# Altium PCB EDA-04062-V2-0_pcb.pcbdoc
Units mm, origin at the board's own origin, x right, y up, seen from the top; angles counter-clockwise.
Board outline 34 x 34 mm, 2 copper layers (Top Layer, Bottom Layer), stack 0.98 mm thick; 20 components, 9 nets, 240 pads, 8 vias.
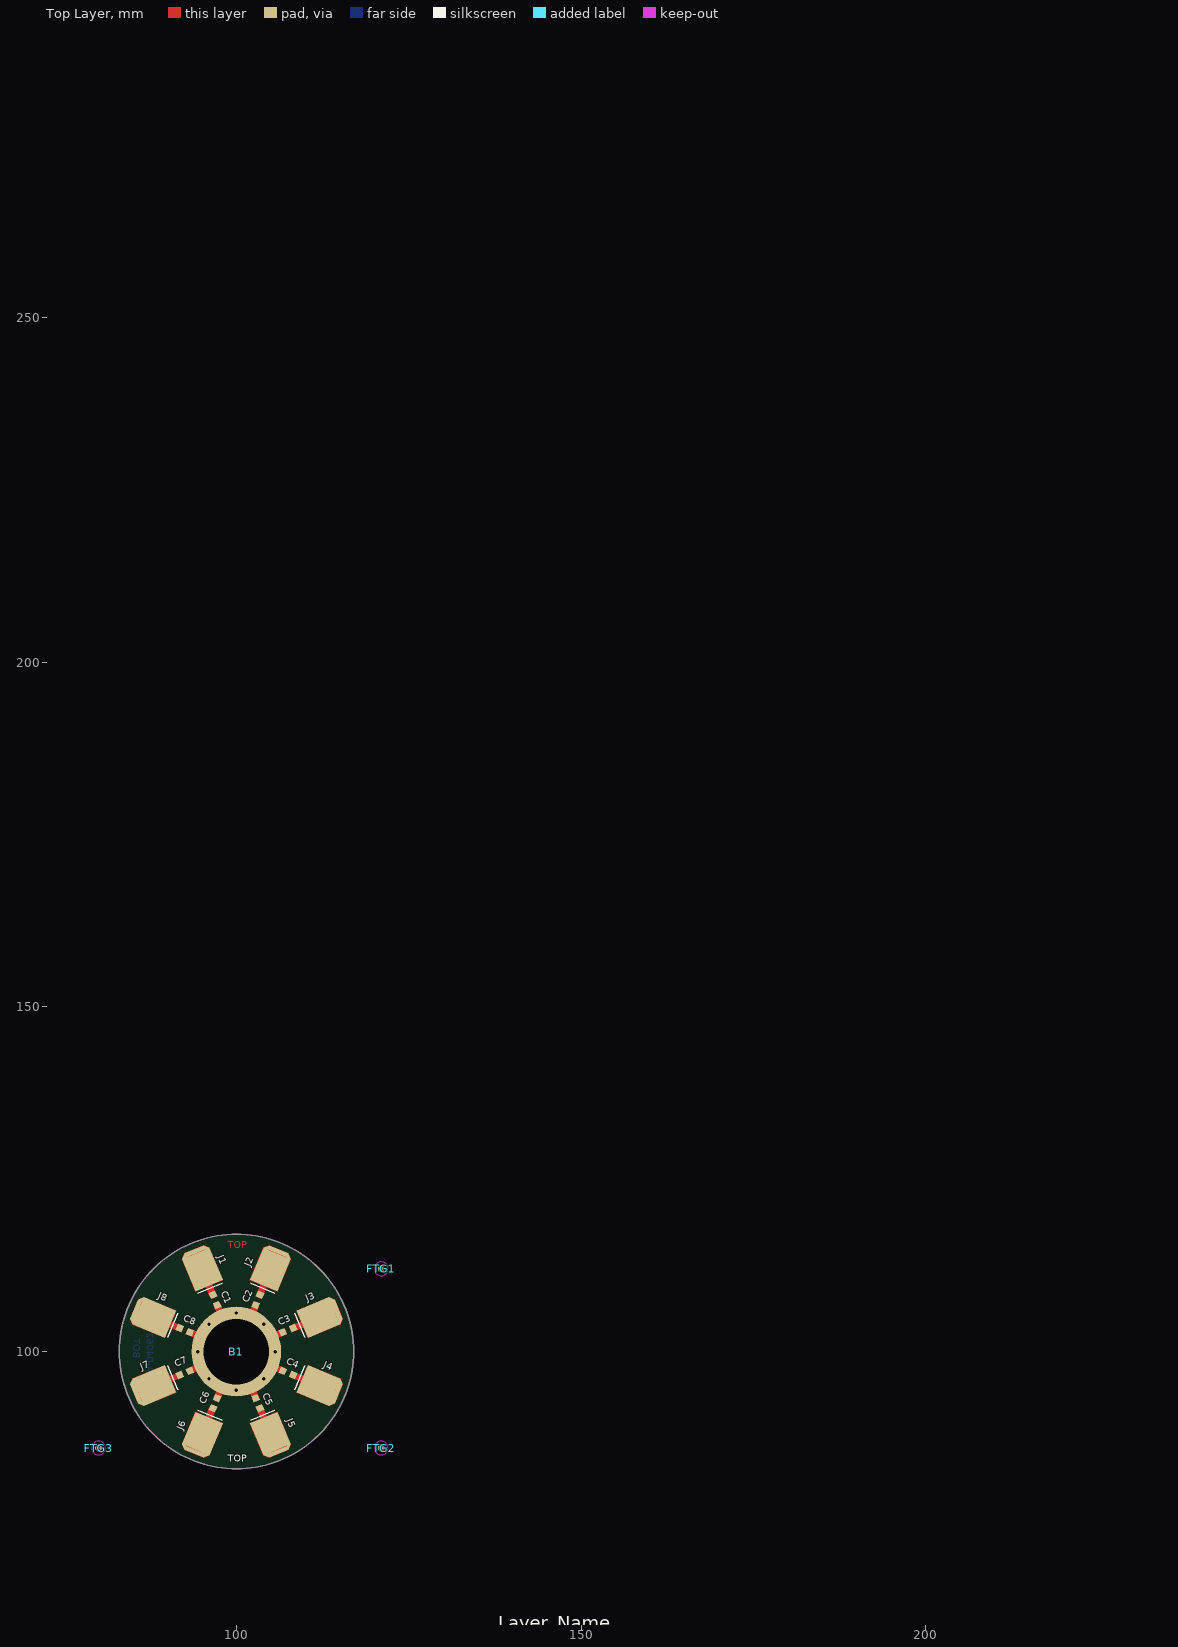
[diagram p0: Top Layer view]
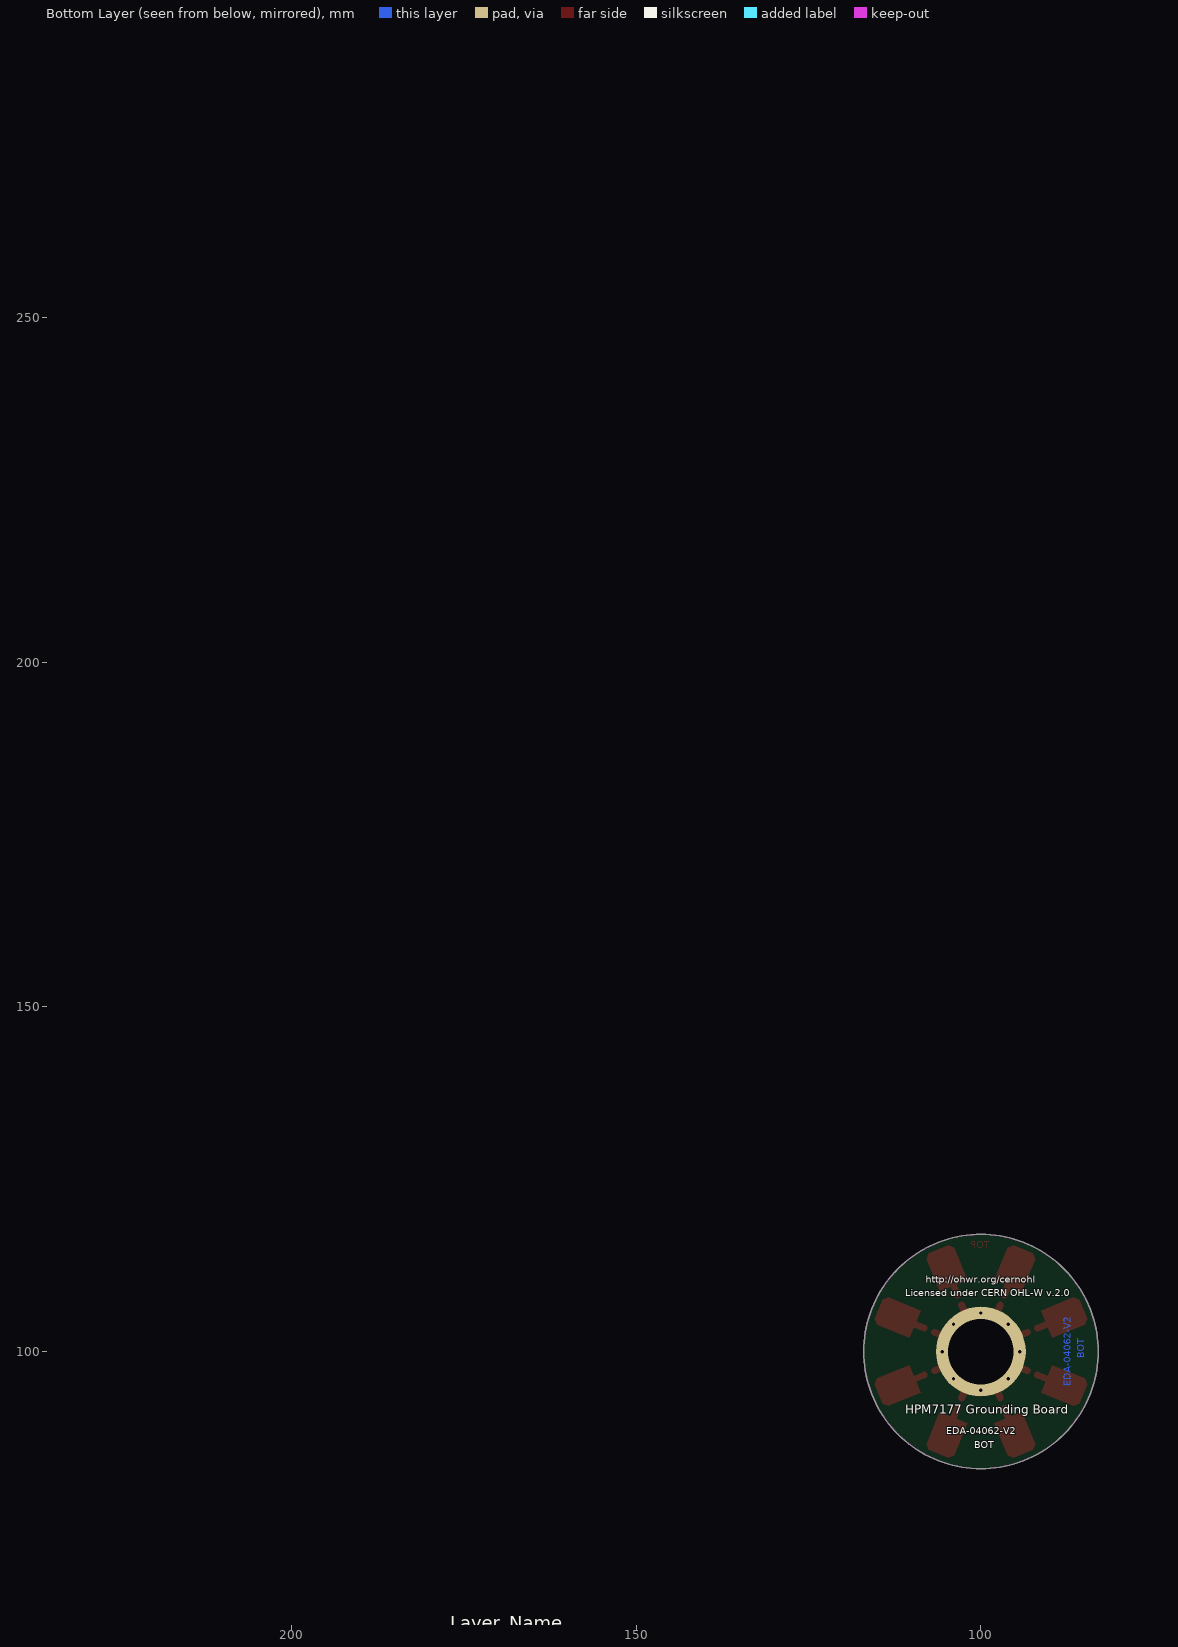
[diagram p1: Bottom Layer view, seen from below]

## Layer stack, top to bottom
Top Solder: solder mask 0.01, Solder Resist, Dk 3.5
Top Layer: signal copper 0.035
Dielectric 1: dielectric 0.91, FR-4, Dk 4.8
Bottom Layer: signal copper 0.035
Bottom Solder: solder mask 0.01, Solder Resist, Dk 3.5

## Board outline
100,83 cw(c100,100) 83,100 cw(c100,100) 100,117 cw(c100,100) 117,100 cw(c100,100)

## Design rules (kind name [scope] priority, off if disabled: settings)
BoardOutlineClearance "Inverted Serig" [((ObjectKind = 'Text') And (IsTextInverted = 'True')) And ((AsMM(InvertedTextBorder) < 0.2) or (AsMM(TextHeight) < 1.5))] p1: gap=2500 ignorepadtopadclearanceinfootprint=FALSE
BoardOutlineClearance "Uncheck Plat" [(PadIsPlated = 'True') And ((HoleDiameter >= PadXSize_AllLayers ) OR (HoleDiameter >= PadYSize_AllLayers))] p2: gap=2500 ignorepadtopadclearanceinfootprint=FALSE
BoardOutlineClearance "Defaut Serig" [(((Layer = 'TopOverlay')  And (StrokeFont = 'Default')) or ((Layer = 'BottomOverlay')  And (StrokeFont = 'Default'))) and not IsTextInverted = 'True'] p3: gap=2500 ignorepadtopadclearanceinfootprint=FALSE
Clearance [All] p1: gap=0.5 ignorepadtopadclearanceinfootprint=FALSE
ComponentClearance ComponentClearance_Overlapping [InComponentClass('NotMounted')] p1: gap=0 collisioncheckmode=3 verticalgap=0 showdistances=FALSE
ComponentClearance [All] p2: gap=0.2 collisioncheckmode=3 verticalgap=0.2 showdistances=FALSE
DiffPairsRouting [All] p1: maxlimit=0.457 minlimit=0.457 mostfreqgap=0.457 toplayer_minwidth=0.229 toplayer_maxwidth=0.229 toplayer_prefwidth=0.229 bottomlayer_minwidth=0.229 bottomlayer_maxwidth=0.229 bottomlayer_prefwidth=0.229 maxuncoupledlength=2.54
FabricationTestPointUsage TestPointUsage [All] p1: valid=0 allowmultiple=FALSE
FabricationTestpoint Testpoint [All] p1: side=3 testpointundercomponent=TRUE minsize=1.016 maxsize=2.54 preferedsize=1.524 minholesize=0 maxholesize=1.016 preferedholesize=0.813 testpointgrid=0.025 allowsidetop=TRUE allowsidebottom=TRUE usegrid=TRUE gridtolerance=0
Height [All] p1: minheight=0 maxheight=25 prefheight=10
HoleSize [All] p1: absolutevalues=TRUE maxlimit=10 minlimit=0.5 maxpercent=80.000 minpercent=20.000
HoleToHoleClearance [All] p1: gap=0.2 allowstackedmicrovias=TRUE
MinimumAnnularRing MinimumAnnularRing_Via [IsVia] p1: minimumring=0.25
MinimumAnnularRing [All] p2: minimumring=0.35
MinimumSolderMaskSliver [All] p1: minsoldermaskwidth=0.25
PermittedLayers [All] p1: toplayerpermitted=TRUE bottomlayerpermitted=TRUE
PlaneClearance [All] p1: clearance=0.5
PlaneConnect PlaneConnect_Direct [InPadClass('Mounting') or IsVia] p1: planeconnectstyle=Direct reliefexpansion=0.508 reliefentries=4 reliefconductorwidth=0.254 reliefairgap=0.254
PlaneConnect [All] p2: planeconnectstyle=Relief reliefexpansion=0.3 reliefentries=4 reliefconductorwidth=0.5 reliefairgap=0.2
PolygonConnect PolygonConnect_Direct [InPadClass('Mounting') or IsVia] p1: connectstyle=Direct reliefconductorwidth=0.254 reliefentries=4 polygonreliefangle="90 Angle" airgapwidth=0.254
PolygonConnect [All] p2: connectstyle=Relief reliefconductorwidth=0.5 reliefentries=4 polygonreliefangle="90 Angle" airgapwidth=0.2
RoomDefinition grounding_pcb [InComponentClass('grounding_pcb')] p1: confinementstyle=ConfineIn formatcopy=TRUE lockcomponents=FALSE outline 78.5,80.5 122.5,80.5 122.5,116.5 78.5,116.5
RoutingVias RoutingVias_NoNet [Not IsElectrical] p1: holewidth=0 width=0 viastyle="Through Hole" minholewidth=0 minwidth=0 maxholewidth=0 maxwidth=0
RoutingVias [All] p2: holewidth=0.5 width=1 viastyle="Through Hole" minholewidth=0.5 minwidth=1 maxholewidth=0.5 maxwidth=1
SilkToSilkClearance [All] p1: silktosilkclearance=0.2
SilkToSolderMaskClearance SilkscreenOverComponentPads [IsPad] p1: minsilkscreentomaskgap=0.225 clearancetoexposedcopper=TRUE
SolderMaskExpansion [All] p1: expansion=0 istentingtop=FALSE
ViasUnderSMD [All] p1: allowed=FALSE
Width [All] p1: maxlimit=2.5 minlimit=0.8 preferedwidth=0.8
18 further rules are at their usual default settings.

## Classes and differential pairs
component class NotMounted: B1

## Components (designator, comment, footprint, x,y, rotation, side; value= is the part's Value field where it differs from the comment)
B1 "Plated Hole" MTG950H1300V8P 100,100 r0 top
C1 "10nF" CAPC1608X87N 96.9,107.483 r292.5 top
C2 "10nF" CAPC1608X87N 103.1,107.483 r247.5 top
C3 "10nF" CAPC1608X87N 107.483,103.1 r202.5 top
C4 "10nF" CAPC1608X87N 107.483,96.9 r157.5 top
C5 "10nF" CAPC1608X87N 103.1,92.517 r112.5 top
C6 "10nF" CAPC1608X87N 96.9,92.517 r67.5 top
C7 "10nF" CAPC1608X87N 92.517,96.9 r22.5 top
C8 "10nF" CAPC1608X87N 92.517,103.1 r337.5 top
FTG1 "Use only in PCB" FIDUCIAL_TOP_C100-200 121,112 r90 top
FTG2 "Use only in PCB" FIDUCIAL_TOP_C100-200 121,86 r90 top
FTG3 "Use only in PCB" FIDUCIAL_TOP_C100-200 80,86 r90 top
J1 "" LAIRD_BMI-C-004 94.949,112.195 r112.5 top
J2 "" LAIRD_BMI-C-004 105.051,112.195 r67.5 top
J3 "" LAIRD_BMI-C-004 112.195,105.051 r22.5 top
J4 "" LAIRD_BMI-C-004 112.195,94.949 r337.5 top
J5 "" LAIRD_BMI-C-004 105.051,87.805 r292.5 top
J6 "" LAIRD_BMI-C-004 94.949,87.805 r247.5 top
J7 "" LAIRD_BMI-C-004 87.805,94.949 r202.5 top
J8 "" LAIRD_BMI-C-004 87.805,105.051 r157.5 top

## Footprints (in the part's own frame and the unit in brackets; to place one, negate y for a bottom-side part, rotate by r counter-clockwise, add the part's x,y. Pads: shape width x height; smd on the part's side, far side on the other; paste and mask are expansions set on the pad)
CAPC1608X87N [mm] "Chip Capacitor, Body 1.6x0.8mm IPC Medium Density"
  rect 0.95x1 smd: 1(-0.8,0) 2(0.8,0)
  body extent -0.87,-0.47 0.88,0.48, height 0.87
FIDUCIAL_TOP_C100-200 [mm] "Round Fiducial Target, Top Layer, 1.0mm, Top Solder 2.0mm, Keepout =2.0mm"
  round 1 smd paste-0.51 mask+0.5: FTG2(0,0)
  Top Layer keep-out circle w0.1: c0,0 r1
LAIRD_BMI-C-004 [mm] "Surface Mount Standard Precision EMI Gasket Grounding Contact, Body 5.97mm x 4.31mm"
  rect 5.08x4.31 smd: 1(-0.325,0)
  rect 0.46x0.919 smd rot 45: 1(2.378,1.667)
  rect 0.46x0.919 smd rot 135: 1(2.378,-1.667)
  rect 0.65x3.01 smd: 1(2.54,0)
  Top Layer region: -2.865,2.155 2.215,2.155 2.865,1.505 2.865,-1.505 2.865,-1.505 2.215,-2.155 -2.865,-2.155
  silkscreen extent -3.23,-1.91 -3.23,1.91, body extent -3.25,-2.16 2.72,2.16, height 5.17
MTG950H1300V8P [mm] "Plated Through Hole: Hole Dia.=9.5mm Pad Dia.=13.0mm + 8 Via Dia.=0.5mm"
  round 13 hole 9.5: 1(0,0)

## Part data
B1: library part PLATED_HOLE9.5_PAD13.0_8VIA, "Single Terminal Socket"
C1 C2 C3 C4 C5 C6 C7 C8: library part CC0603_10NF_250V_10%_X7R_KEMET_C0603C103KARACAUTO, "Non-polarised capacitor", Case=0603, Manufacturer=KEMET, Manufacturer Part Number=C0603C103KARACAUTO, Tolerance=±10%, Voltage=250V
FTG1 FTG2 FTG3: library part FIDUCIAL_TARGET_C100-200, "Fiducial Target"
J1 J2 J3 J4 J5 J6 J7 J8: library part LAIRD_BMI-C-004, "Spring Contact", Manufacturer=LAIRD

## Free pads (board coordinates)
  round 3.5 on Mech9: 1(78,66.1) 1(230,66.1)
  round 1 on Mech9: 1(80,86) 1(121,86) 1(121,112)
  round 0.8 on Mech9: 1(84.64,92.297) 1(84.64,145.897) 1(84.64,199.497) 1(84.64,253.097) 1(85.357,91.273) 1(85.357,144.873) 1(85.357,198.473) 1(85.357,252.073) 1(86.074,90.249) 1(86.074,143.849) 1(86.074,197.449) 1(86.074,251.049) 1(86.791,89.225) 1(86.791,142.825) 1(86.791,196.425) 1(86.791,250.025) 1(87.508,88.201) 1(87.508,141.801) 1(87.508,195.401) 1(87.508,249.001) 1(97.5,117) 1(97.5,170.6) 1(97.5,224.2) 1(97.5,277.8) 1(98.75,117) 1(98.75,170.6) 1(98.75,224.2) 1(98.75,277.8) 1(100,117) 1(100,170.6) 1(100,224.2) 1(100,277.8) 1(101.25,117) 1(101.25,170.6) 1(101.25,224.2) 1(101.25,277.8) 1(102.5,117) 1(102.5,170.6) 1(102.5,224.2) 1(102.5,277.8) 1(112.492,88.201) 1(112.492,141.801) 1(112.492,195.401) 1(112.492,249.001) 1(113.209,89.225) 1(113.209,142.825) 1(113.209,196.425) 1(113.209,250.025) 1(113.926,90.249) 1(113.926,143.849) 1(113.926,197.449) 1(113.926,251.049) 1(114.643,91.273) 1(114.643,144.873) 1(114.643,198.473) 1(114.643,252.073) 1(115.36,92.297) 1(115.36,145.897) 1(115.36,199.497) 1(115.36,253.097) 1(138.64,92.297) 1(138.64,145.897) 1(138.64,199.497) 1(138.64,253.097) 1(139.357,91.273) 1(139.357,144.873) 1(139.357,198.473) 1(139.357,252.073) 1(140.074,90.249) 1(140.074,143.849) 1(140.074,197.449) 1(140.074,251.049) 1(140.791,89.225) 1(140.791,142.825) 1(140.791,196.425) 1(140.791,250.025) 1(141.508,88.201) 1(141.508,141.801) 1(141.508,195.401) 1(141.508,249.001) 1(151.5,117) 1(151.5,170.6) 1(151.5,224.2) 1(151.5,277.8) 1(152.75,117) 1(152.75,170.6) 1(152.75,224.2) 1(152.75,277.8) 1(154,117) 1(154,170.6) 1(154,224.2) 1(154,277.8) 1(155.25,117) 1(155.25,170.6) 1(155.25,224.2) 1(155.25,277.8) 1(156.5,117) 1(156.5,170.6) 1(156.5,224.2) 1(156.5,277.8) 1(166.492,88.201) 1(166.492,141.801) 1(166.492,195.401) 1(166.492,249.001) 1(167.209,89.225) 1(167.209,142.825) 1(167.209,196.425) 1(167.209,250.025) 1(167.926,90.249) 1(167.926,143.849) 1(167.926,197.449) 1(167.926,251.049) 1(168.643,91.273) 1(168.643,144.873) 1(168.643,198.473) 1(168.643,252.073) 1(169.36,92.297) 1(169.36,145.897) 1(169.36,199.497) 1(169.36,253.097) 1(192.64,92.297) 1(192.64,145.897) 1(192.64,199.497) 1(192.64,253.097) 1(193.357,91.273) 1(193.357,144.873) 1(193.357,198.473) 1(193.357,252.073) 1(194.074,90.249) 1(194.074,143.849) 1(194.074,197.449) 1(194.074,251.049) 1(194.791,89.225) 1(194.791,142.825) 1(194.791,196.425) 1(194.791,250.025) 1(195.508,88.201) 1(195.508,141.801) 1(195.508,195.401) 1(195.508,249.001) 1(205.5,117) 1(205.5,170.6) 1(205.5,224.2) 1(205.5,277.8) 1(206.75,117) 1(206.75,170.6) 1(206.75,224.2) 1(206.75,277.8) 1(208,117) 1(208,170.6) 1(208,224.2) 1(208,277.8) 1(209.25,117) 1(209.25,170.6) 1(209.25,224.2) 1(209.25,277.8) 1(210.5,117) 1(210.5,170.6) 1(210.5,224.2) 1(210.5,277.8) 1(220.492,88.201) 1(220.492,141.801) 1(220.492,195.401) 1(220.492,249.001) 1(221.209,89.225) 1(221.209,142.825) 1(221.209,196.425) 1(221.209,250.025) 1(221.926,90.249) 1(221.926,143.849) 1(221.926,197.449) 1(221.926,251.049) 1(222.643,91.273) 1(222.643,144.873) 1(222.643,198.473) 1(222.643,252.073) 1(223.36,92.297) 1(223.36,145.897) 1(223.36,199.497) 1(223.36,253.097)
  round 2 on Mech9: 1(88,66.1) 1(220,66.1) 1(220,287.7)

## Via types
v1: diameter 1, hole 0.5, Top Layer to Bottom Layer, tented both sides, 8 vias

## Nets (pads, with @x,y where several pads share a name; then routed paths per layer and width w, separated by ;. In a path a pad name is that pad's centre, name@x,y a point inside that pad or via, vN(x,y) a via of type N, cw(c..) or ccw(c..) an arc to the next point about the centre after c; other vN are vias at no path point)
GND: B1.1 C1.2 C2.2 C3.2 C4.2 C5.2 C6.2 C7.2 C8.2 | length 103.4
  Top Layer w0.889: v1(94.375,100) B1.1 ; v1(96.023,96.023) B1.1 ; v1(96.023,103.977) B1.1 ; v1(100,94.375) B1.1 ; v1(100,105.588) B1.1 ; v1(103.977,96.023) B1.1 ; v1(103.977,103.977) B1.1 ; v1(105.625,100) B1.1
  Top Layer w1: C7.2 B1.1 ; C8.2 B1.1 ; C6.2 B1.1 ; C1.2 B1.1 ; C5.2 B1.1 ; C2.2 B1.1 ; C4.2 B1.1 ; C3.2 B1.1
NetC1_1: C1.1 J1.1 | length 4
  Top Layer w1: J1.1@95.073,111.895 C1.1
NetC2_1: C2.1 J2.1 | length 4
  Top Layer w1: C2.1 J2.1@104.927,111.895
NetC3_1: C3.1 J3.1 | length 4
  Top Layer w1: C3.1 J3.1@111.895,104.927
NetC4_1: C4.1 J4.1 | length 4
  Top Layer w1: C4.1 J4.1@111.895,95.073
NetC5_1: C5.1 J5.1 | length 4
  Top Layer w1: C5.1 J5.1@104.927,88.105
NetC6_1: C6.1 J6.1 | length 4
  Top Layer w1: J6.1@95.073,88.105 C6.1
NetC7_1: C7.1 J7.1 | length 4
  Top Layer w1: J7.1@88.105,95.073 C7.1
NetC8_1: C8.1 J8.1 | length 4
  Top Layer w1: J8.1@88.105,104.927 C8.1
pads on no net: FTG1.FTG2 FTG2.FTG2 FTG3.FTG2

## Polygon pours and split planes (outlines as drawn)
no net on Panelisation "CM-eq" (solid): 77.7,86 74.3,87 75.3,86 74.3,85

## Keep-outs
Keep-Out Layer:
  circle w0.1: c100,100 r17

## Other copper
Top Layer:
  text "TOP" at 98.75,115 h1
  text ".Layer_Name" at 140.335,34.29 h1.91 r45
  text "1" at 139.382,29.21 h2.54
Bottom Layer:
  text "BOT" at 85,99 h1 r270
  text "EDA-04062-V2" at 87,95 h1 r270
  text ".Layer_Name" at 157.48,46.355 h1.91 r45
  text "2" at 143.827,29.21 h2.54

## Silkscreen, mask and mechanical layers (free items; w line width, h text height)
Top Overlay:
  text "TOP" at 98.75,84 h1
  text ".Layer_Name" at 137.16,59.69 h1.91
Bottom Overlay:
  text "http://ohwr.org/cernohl" at 108,110 h1
  text "Licensed under CERN OHL-W v.2.0" at 111,108 h1
  text "HPM7177 Grounding Board" at 111,91 h1.25
  text "EDA-04062-V2" at 105,88 h1
  text "BOT" at 101,86 h1
  text ".Layer_Name" at 177.8,59.69 h1.91
Top Paste:
  text ".Layer_Name" at 137.16,54.61 h1.91
Bottom Paste:
  text ".Layer_Name" at 177.8,54.61 h1.91
Top Solder:
  text ".Layer_Name" at 137.16,57.15 h1.91
Bottom Solder:
  text ".Layer_Name" at 177.8,57.15 h1.91
Mechanical 1:
  circle w0.8: c100,100 r17
Mechanical 2:
  text "Components" at 100.33,59.69 h1.91
  text ".Component_Count" at 118.11,59.69 h1.91
  text "Pins" at 100.33,57.15 h1.91
  text ".Pad_Count" at 118.11,57.15 h1.91
  text "Vias" at 100.33,54.61 h1.91
  text ".Via_Count" at 118.11,54.61 h1.91
  text "Holes" at 100.33,52.07 h1.91
  text ".Hole_Count" at 118.11,52.07 h1.91
  text "Nets" at 100.33,49.53 h1.91
  text ".Net_Count" at 118.11,49.53 h1.91
Mechanical 4:
  lines w0.2: 87.305,94.949 87.805,94.949 87.805,94.449 ; 87.305,105.051 87.805,105.051 87.805,104.551 ; 92.017,96.9 92.517,96.9 92.517,96.4 ; 92.017,103.1 92.517,103.1 92.517,102.6 ; 94.449,87.805 94.949,87.805 94.949,87.305 ; 94.449,112.195 94.949,112.195 94.949,111.695 ; 96.4,92.517 96.9,92.517 96.9,92.017 ; 96.4,107.483 96.9,107.483 96.9,106.983 ; 99.5,100 100,100 100,99.5 ; 102.6,92.517 103.1,92.517 103.1,92.017 ; 102.6,107.483 103.1,107.483 103.1,106.983 ; 104.551,87.805 105.051,87.805 105.051,87.305 ; 104.551,112.195 105.051,112.195 105.051,111.695 ; 106.983,96.9 107.483,96.9 107.483,96.4 ; 106.983,103.1 107.483,103.1 107.483,102.6 ; 111.695,94.949 112.195,94.949 112.195,94.449 ; 111.695,105.051 112.195,105.051 112.195,104.551
Corners:
  lines w0.2: 78,83 83,83 83,78 ; 78,117 83,117 83,122 ; 117,78 117,83 122,83 ; 117,122 117,117 122,117
  lines w0.254: 142.24,27.94 142.24,33.02 ; 137.16,27.94 137.16,33.02 147.32,33.02 147.32,27.94 137.16,27.94
Title Block:
  circle w0.305: c75.565,40.64 r3.81
  lines w0.254: 73.66,39.378 ccw(c78.105,39.37) 74.373,41.784 ; 82.55,39.37 82.55,43.815 ; 85.09,36.195 127,36.195 ; 85.09,39.37 127,39.37 ; 85.09,42.545 127,42.545 ; 99.06,33.02 99.06,45.72 ; 71.12,33.02 71.12,45.72 83.82,45.72 83.82,33.02 71.12,33.02 ; 85.09,33.02 85.09,45.72 127,45.72 127,33.02 85.09,33.02
  lines w0.305: 72.009,39.268 73.025,36.195 ; 75.057,33.147 78.13,37.821 ; 75.565,44.45 83.185,45.085 ; 79.299,41.402 81.915,33.02
  text "Number" at 86.36,43.18 h1.91
  text "EDA-04062-V2" at 100.33,43.18 h1.91
  text "Drawn By" at 86.36,40.005 h1.91
  text "N. Beev" at 100.33,40.005 h1.91
  text "CERN" at 72.39,39.751 h2.54
  text "DATE" at 86.36,36.83 h1.91
  text "04-04-2019" at 100.33,36.83 h1.91
  text "(08/07/2021)" at 113,34 h1.4
  text "Checked" at 86.36,33.655 h1.91
  text "B. Civel" at 100.33,33.655 h1.91
  text "Print Date" at 86.36,30.48 h1.27
  text ".Print_Date" at 101.6,30.48 h1.27
  text ".Print_Time" at 114.3,30.48 h1.27
  text ".Print_Scale" at 86.36,28.575 h1.27
  text "Altium Designer Rev" at 86.36,26.67 h1.27
  text "'.Application_BuildNumber'" at 105.41,26.67 h1.27
Mechanical 7:
  circle w0.2: c100,100 r6.5
  lines w0.2: 84.582,95.243 85.734,92.462 86.583,92.11 91.276,94.054 89.627,98.036 84.934,96.092 84.582,95.243 ; 84.582,104.757 84.934,103.908 89.627,101.964 91.276,105.946 86.583,107.89 85.734,107.538 84.582,104.757 ; 91.147,96.874 92.025,97.238 92.408,96.314 91.53,95.95 91.147,96.874 ; 91.147,103.126 92.025,102.762 92.408,103.686 91.53,104.05 91.147,103.126 ; 92.11,86.583 94.054,91.276 98.036,89.627 96.092,84.934 95.243,84.582 92.462,85.734 92.11,86.583 ; 92.11,113.417 92.462,114.266 95.243,115.418 96.092,115.066 98.036,110.373 94.054,108.724 92.11,113.417 ; 92.625,97.487 93.503,97.85 93.886,96.926 93.008,96.563 92.625,97.487 ; 92.625,102.513 93.503,102.15 93.886,103.074 93.008,103.437 92.625,102.513 ; 95.95,91.53 96.314,92.408 97.238,92.025 96.874,91.147 95.95,91.53 ; 95.95,108.47 96.314,107.592 97.238,107.975 96.874,108.853 95.95,108.47 ; 96.563,93.008 96.926,93.886 97.85,93.503 97.487,92.625 96.563,93.008 ; 96.563,106.992 96.926,106.114 97.85,106.497 97.487,107.374 96.563,106.992 ; 101.964,89.627 103.908,84.934 104.757,84.582 107.538,85.734 107.89,86.583 105.946,91.276 101.964,89.627 ; 101.964,110.373 103.908,115.066 104.757,115.418 107.538,114.266 107.89,113.417 105.946,108.724 101.964,110.373 ; 102.15,93.503 102.513,92.625 103.437,93.008 103.074,93.886 102.15,93.503 ; 102.15,106.497 103.074,106.114 103.437,106.992 102.513,107.375 102.15,106.497 ; 102.762,92.025 103.126,91.147 104.05,91.53 103.686,92.408 102.762,92.025 ; 102.762,107.975 103.686,107.592 104.05,108.47 103.126,108.853 102.762,107.975 ; 106.114,96.926 106.992,96.563 107.375,97.487 106.497,97.85 106.114,96.926 ; 106.114,103.074 106.497,102.15 107.375,102.513 106.992,103.437 106.114,103.074 ; 107.592,96.314 108.47,95.95 108.853,96.874 107.975,97.238 107.592,96.314 ; 107.592,103.686 107.975,102.762 108.853,103.126 108.47,104.05 107.592,103.686 ; 108.724,94.054 113.417,92.11 114.266,92.462 115.418,95.243 115.066,96.092 110.373,98.036 108.724,94.054 ; 108.724,105.946 113.417,107.89 114.266,107.538 115.418,104.757 115.066,103.908 110.373,101.964 108.724,105.946
Notvisible:
  circle w0.203: c104.995,111.975 r2.775
  circle w0.3: c92.062,108.49 r0.2
  lines w0.05: 92.062,107.19 107.937,114.81 ; 92.062,107.19 107.937,107.19 ; 92.062,107.19 92.062,114.81 ; 92.062,114.81 107.937,107.19 ; 92.062,114.81 107.937,114.81 ; 107.937,107.19 107.937,114.81
  lines w0.2: 98.705,109.845 98.705,110.845 ; 98.705,111.445 98.705,112.345
  lines w0.203: 92.062,108.49 92.062,107.19 99.682,107.19 99.682,110.845 ; 95.804,110.045 cw(c96.324,109.471) 96.304,110.245 97.805,110.245 97.805,110.745 97.105,110.745 cw(c97.071,110.928) 96.905,110.845 ; 95.805,110.045 95.805,110.845 96.905,110.845 ; 98.705,109.845 cw(c98.205,109.957) 98.205,109.445 96.305,109.445 cw(c96.372,110.124) 95.805,109.745 cw(c95.463,109.853) 95.105,109.845 95.105,111.545 94.805,111.045 cw(c94.455,111.185) 94.105,111.045 93.805,111.545 93.805,109.845 cw(c93.455,109.795) 93.105,109.845 93.105,112.545 cw(c93.655,112.238) 94.205,112.545 94.455,112.045 94.705,112.545 cw(c95.255,112.178) 95.805,112.545 cw(c96.305,112.278) 96.305,112.845 98.205,112.845 cw(c97.872,112.012) 98.705,112.345 ; 98.705,110.845 99.669,110.845 ; 98.705,111.445 99.682,111.445 99.682,114.75 104.996,114.75 ; 100.547,114.063 101.019,110.75 ; 101.1,107.495 102.294,112.606 ; 102.945,110.106 105.549,107.25 ; 105.747,113.081 ccw(c103.765,111.142) 106.525,110.873 ; 106.95,108.657 107.668,111.229 ; 95.805,111.445 95.805,112.245 ccw(c96.305,112.77) 96.305,112.045 97.805,112.045 97.805,111.545 97.105,111.545 ccw(c97.071,111.362) 96.905,111.445 95.805,111.445
  lines w0.254: 137.16,34.29 157.48,34.29 ; 140.335,34.29 147.955,41.91 ; 145.415,34.29 153.035,41.91 ; 150.495,34.29 158.115,41.91 ; 155.575,34.29 163.195,41.91
  text "TE/MPE" at 98.412,113.54 h1
  text "CERN" at 107.112,111.381 h1.25
  text "NB/JMW" at 98.73,107.825 h1
Panelisation:
  drawing of 318 lines, arcs and shapes, not listed
  text "Area without Copper & without Solder Mask on both Sides" at 116.5,290.2 h1.75
  text "Ø2mm Not Drilled" at 240.6,254.3 h3 r90
  text "3x OPTICAL TARGET" at 236.6,251.3 h3 r90
  text "Dimensions are rounded to 0.1mm. Gerber data is the reference" at 242.6,138.9 h3 r90
  text "ALL DIMENSIONS ARE IN MILLIMETERS" at 239.1,134.4 h5 r90
  text "Not Plated Holes" at 147.5,109 h1.5
  text "Ø3.5 ±0.05" at 236.6,76.5 h3 r90
  text "NOT PLATED HOLE" at 240.6,76.5 h3 r90
  text ".Layer_Name" at 165.26,33.98 h1.91
  text "PANEL of 12 PCBs in staggered rows/columns with 3 external optical targets (dia 1mm) per PCB" at 63,22 h2.5
  text "Please, repeat the 3 fiducial targets outside the PCB to each repeated PCB (not drilled, only on TOP layer)" at 63,18 h1.5
Mechanical 10:
  drawing of 180 lines, arcs and shapes, not listed
Mechanical 11:
  drawing of 1363 lines, arcs and shapes, not listed
Drill Drawing:
  circle w0.25: c66.328,132.708 r0.833
  lines w0.25: 65.495,135.625 67.161,135.625 67.161,137.292 65.495,137.292 65.495,135.625
  lines w0.5: 64,130.75 133.586,130.75 ; 64,138.25 133.586,138.25 ; 76.565,127 76.565,142 ; 86.427,127 86.427,142 ; 110.259,127 110.259,142 ; 120.181,127 120.181,142 ; 64,127 133.586,127 133.586,142 64,142 64,127
  text "Symbol" at 66.25,139.375 h1.8
  text "Count" at 77.69,139.375 h1.8
  text "Hole Size" at 87.552,139.375 h1.8
  text "Plated" at 111.384,139.375 h1.8
  text "Via/Pad" at 121.306,139.375 h1.8
  text "8" at 77.69,135.625 h1.5
  text "0.50mm (19.69mil)" at 87.552,135.625 h1.5
  text "PTH" at 111.384,135.625 h1.5
  text "Via" at 121.306,135.625 h1.5
  text "1" at 77.69,131.875 h1.5
  text "9.50mm (374.02mil)" at 87.552,131.875 h1.5
  text "PTH" at 111.384,131.875 h1.5
  text "Pad" at 121.306,131.875 h1.5
  text "9 Total" at 77.69,128.125 h1.5
  text "General tolerances +/-0.05mm unless otherwise stated" at 65,124 h1.5

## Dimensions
100,83 to 100,100 on Drill Drawing
83,100 to 100,100 on Drill Drawing
63,58.6 to 63,66.1 on Panelisation
63,58.6 to 84.591,89.561 on Panelisation
63,58.6 to 99.5,83 on Panelisation
63,58.6 to 78,63.35 on Panelisation
136,117 to 136,119.4 on Panelisation
101.25,117 to 100,117 on Panelisation
154,117 to 154,112.99 on Panelisation
151,119.4 to 157,119.4 on Panelisation
100,100 to 115.03,115.03 on Mechanical 2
